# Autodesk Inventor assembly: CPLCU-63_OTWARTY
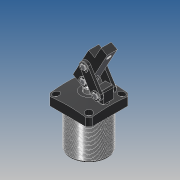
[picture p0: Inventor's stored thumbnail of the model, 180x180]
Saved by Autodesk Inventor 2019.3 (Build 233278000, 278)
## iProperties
Created: 2010-03
Part Number: CPLCU-63_OTWARTY
Material: Ogólny
Document SubType Name: Assembly
Designer: CADENGINEERING4
Sending System: PRO/ENGINEER BY PARAMETRIC TECHNOLOGY CORPORATION, 2007170
Preprocessor: PRO/ENGINEER BY PARAMETRIC TECHNOLOGY CORPORATION, 2007170
Title: CPLCU-63_ASM
Author: Administrator
Revision Number: 6LAST_VERSION
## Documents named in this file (10)
- E:\SERWER_ZAPAS\MODELE brakujace\PNEUMATIC\CPLCU(STEP)\cplcu-63_asm\CPLCU-63_OTWARTY.iam
- E:\SERWER_ZAPAS\MODELE brakujace\PNEUMATIC\CPLCU(STEP)\cplcu-63_asm\CPLCU-63-07.ipt
- E:\SERWER_ZAPAS\MODELE brakujace\PNEUMATIC\CPLCU(STEP)\cplcu-63_asm\CPLCU-63-06.ipt
- E:\SERWER_ZAPAS\MODELE brakujace\PNEUMATIC\CPLCU(STEP)\cplcu-63_asm\CPLCU-63-05.ipt
- E:\SERWER_ZAPAS\MODELE brakujace\PNEUMATIC\CPLCU(STEP)\cplcu-63_asm\CPLCU-63-01.ipt
- E:\SERWER_ZAPAS\MODELE brakujace\PNEUMATIC\CPLCU(STEP)\cplcu-63_asm\CPLCU-63-02.ipt
- E:\SERWER_ZAPAS\MODELE brakujace\PNEUMATIC\CPLCU(STEP)\cplcu-63_asm\CPLCU-63-08.ipt
- E:\SERWER_ZAPAS\MODELE brakujace\PNEUMATIC\CPLCU(STEP)\cplcu-63_asm\CPLCU-63-03.ipt
- E:\SERWER_ZAPAS\MODELE brakujace\PNEUMATIC\CPLCU(STEP)\cplcu-63_asm\CPLCU-63-04.ipt
- E:\SERWER_ZAPAS\MODELE brakujace\PNEUMATIC\CPLCU(STEP)\cplcu-63_asm\CPLCU-50-08.ipt
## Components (21 placed, 21 different names)
1. CPLCU-63-07_0 — Zestawiające:22, Zestawiające:26
2. CPLCU-63-06_1 — Zestawiające:13, Zestawiające:14, Zestawiające:15, Zestawiające:16, Zestawiające:20, Zestawiające:22, Zestawiające:26
3. CPLCU-63-05_2 — Zestawiające:1, Zestawiające:2, Zestawiające:5, Zestawiające:6
4. CPLCU-63-01_3 — Zestawiające:23, Zestawiające:24, Zestawiające:25
5. CPLCU-63-02_4 — Zestawiające:3, Zestawiające:4, Zestawiające:5, Zestawiające:12, Zestawiające:24
6. CPLCU-63-02_5 — Zestawiające:3, Zestawiające:4, Zestawiające:6, Zestawiające:7
7. CPLCU-63-08_6 — Zestawiające:14, Zestawiające:15, Zestawiające:19, Zestawiające:21
8. CPLCU-63-08_7 — Zestawiające:2, Zestawiające:9
9. CPLCU-63-08_8 — Zestawiające:7
10. CPLCU-63-08_9 — Zestawiające:13, Zestawiające:16, Zestawiające:17, Zestawiające:18, Zestawiające:25
11. CPLCU-63-08_10
12. CPLCU-63-08_11 — Zestawiające:1, Zestawiające:8
13. CPLCU-63-03_12 — Równoległe:4, Równoległe:5, Zestawiające:20
14. CPLCU-63-04_13 — Równoległe:1, Zestawiające:8, Zestawiające:9, Zestawiające:10, Zestawiające:11, Zestawiające:12, Zestawiające:23
15. CPLCU-63-04_14 — Równoległe:1
16. CPLCU-50-08_15 — Równoległe:5, Zestawiające:19, Zestawiające:21
17. CPLCU-50-08_16 — Równoległe:4, Zestawiające:17, Zestawiające:18
18. CPLCU-50-08_17 — Równoległe:3, Zestawiające:11
19. CPLCU-50-08_18 — Równoległe:3
20. CPLCU-50-08_19 — Równoległe:2, Zestawiające:10
21. CPLCU-50-08_20 — Równoległe:2
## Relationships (31: Mate 26, Flush 5)
- Równoległe:1 [Flush]: CPLCU-63-04_13 ↔ CPLCU-63-04_14
- Równoległe:2 [Flush]: CPLCU-50-08_19 ↔ CPLCU-50-08_20
- Równoległe:3 [Flush]: CPLCU-50-08_17 ↔ CPLCU-50-08_18
- Zestawiające:1 [Mate]: CPLCU-63-05_2 ↔ CPLCU-63-08_11
- Zestawiające:2 [Mate]: CPLCU-63-05_2 ↔ CPLCU-63-08_7
- Zestawiające:3 [Mate]: CPLCU-63-02_4 ↔ CPLCU-63-02_5
- Zestawiające:4 [Mate]: CPLCU-63-02_4 ↔ CPLCU-63-02_5
- Zestawiające:5 [Mate]: CPLCU-63-05_2 ↔ CPLCU-63-02_4
- Zestawiające:6 [Mate]: CPLCU-63-05_2 ↔ CPLCU-63-02_5
- Zestawiające:7 [Mate]: CPLCU-63-02_5 ↔ CPLCU-63-08_8
- Zestawiające:8 [Mate]: CPLCU-63-08_11 ↔ CPLCU-63-04_13
- Zestawiające:9 [Mate]: CPLCU-63-08_7 ↔ CPLCU-63-04_13
- Zestawiające:10 [Mate]: CPLCU-63-04_13 ↔ CPLCU-50-08_19
- Zestawiające:11 [Mate]: CPLCU-63-04_13 ↔ CPLCU-50-08_17
- Zestawiające:12 [Mate]: CPLCU-63-02_4 ↔ CPLCU-63-04_13
- Równoległe:4 [Flush]: CPLCU-63-03_12 ↔ CPLCU-50-08_16
- Równoległe:5 [Flush]: CPLCU-63-03_12 ↔ CPLCU-50-08_15
- Zestawiające:13 [Mate]: CPLCU-63-06_1 ↔ CPLCU-63-08_9
- Zestawiające:14 [Mate]: CPLCU-63-06_1 ↔ CPLCU-63-08_6
- Zestawiające:15 [Mate]: CPLCU-63-06_1 ↔ CPLCU-63-08_6
- Zestawiające:16 [Mate]: CPLCU-63-06_1 ↔ CPLCU-63-08_9
- Zestawiające:17 [Mate]: CPLCU-63-08_9 ↔ CPLCU-50-08_16
- Zestawiające:18 [Mate]: CPLCU-63-08_9 ↔ CPLCU-50-08_16
- Zestawiające:19 [Mate]: CPLCU-63-08_6 ↔ CPLCU-50-08_15
- Zestawiające:20 [Mate]: CPLCU-63-06_1 ↔ CPLCU-63-03_12
- Zestawiające:21 [Mate]: CPLCU-63-08_6 ↔ CPLCU-50-08_15
- Zestawiające:22 [Mate]: CPLCU-63-07_0 ↔ CPLCU-63-06_1
- Zestawiające:23 [Mate]: CPLCU-63-01_3 ↔ CPLCU-63-04_13
- Zestawiające:24 [Mate]: CPLCU-63-01_3 ↔ CPLCU-63-02_4
- Zestawiające:25 [Mate]: CPLCU-63-01_3 ↔ CPLCU-63-08_9
- Zestawiające:26 [Mate]: CPLCU-63-07_0 ↔ CPLCU-63-06_1
